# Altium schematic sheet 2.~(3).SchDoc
size 609 x 444 mm
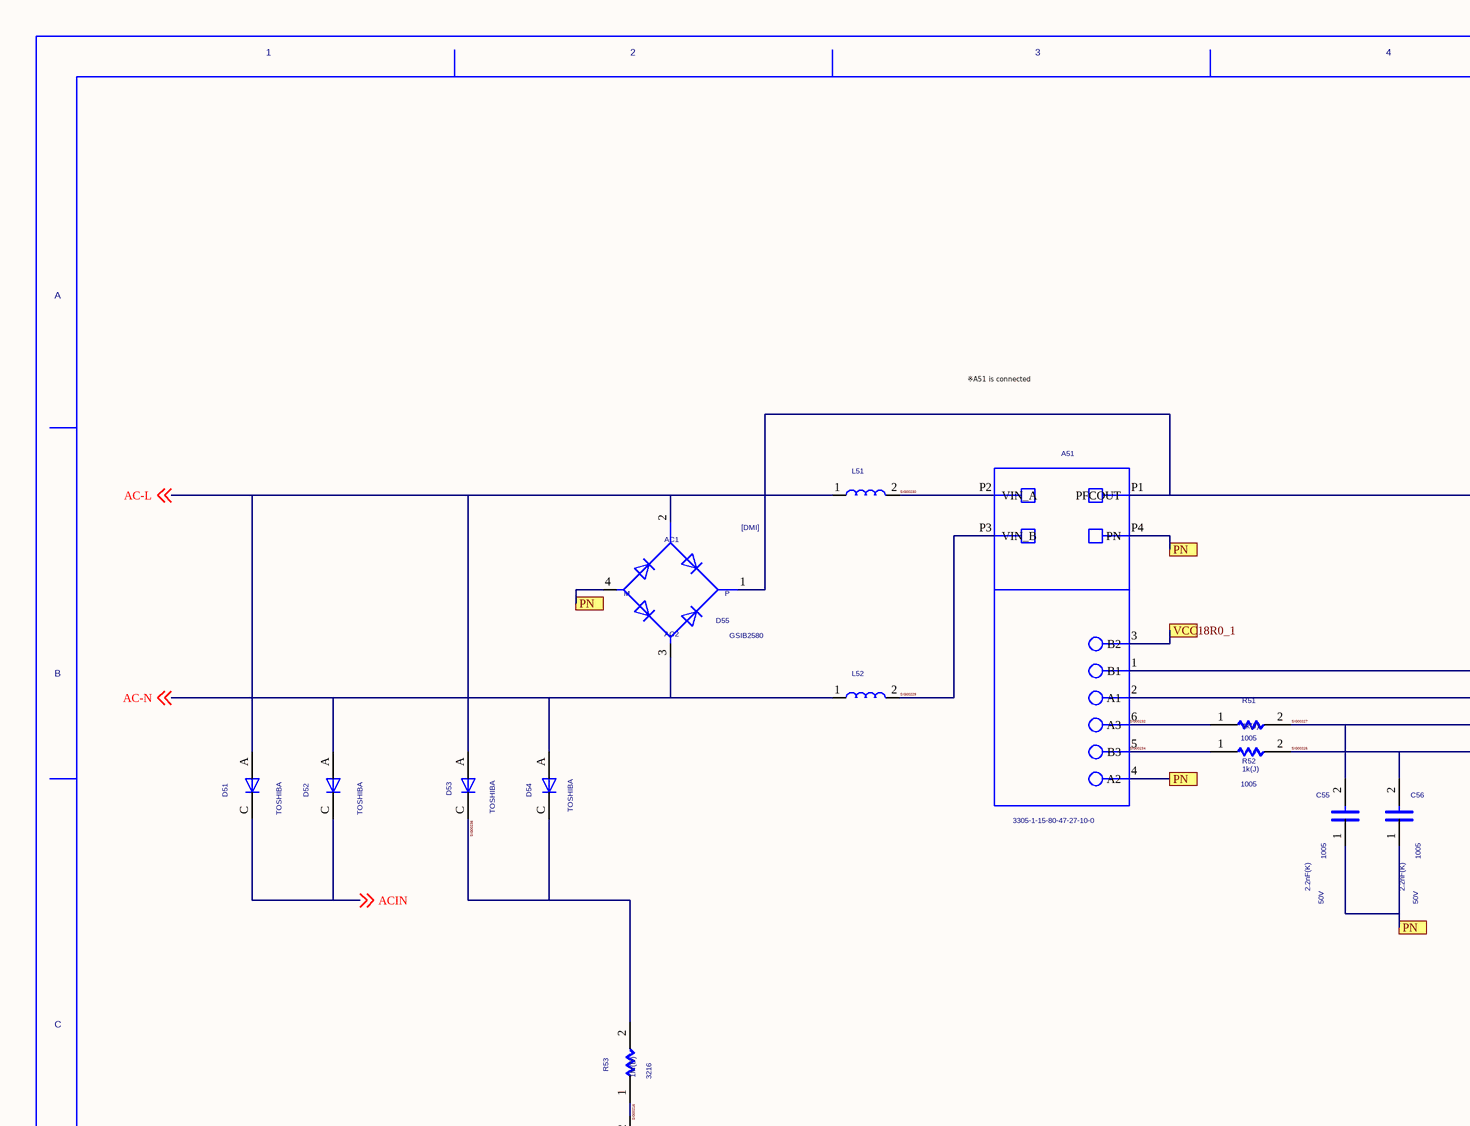
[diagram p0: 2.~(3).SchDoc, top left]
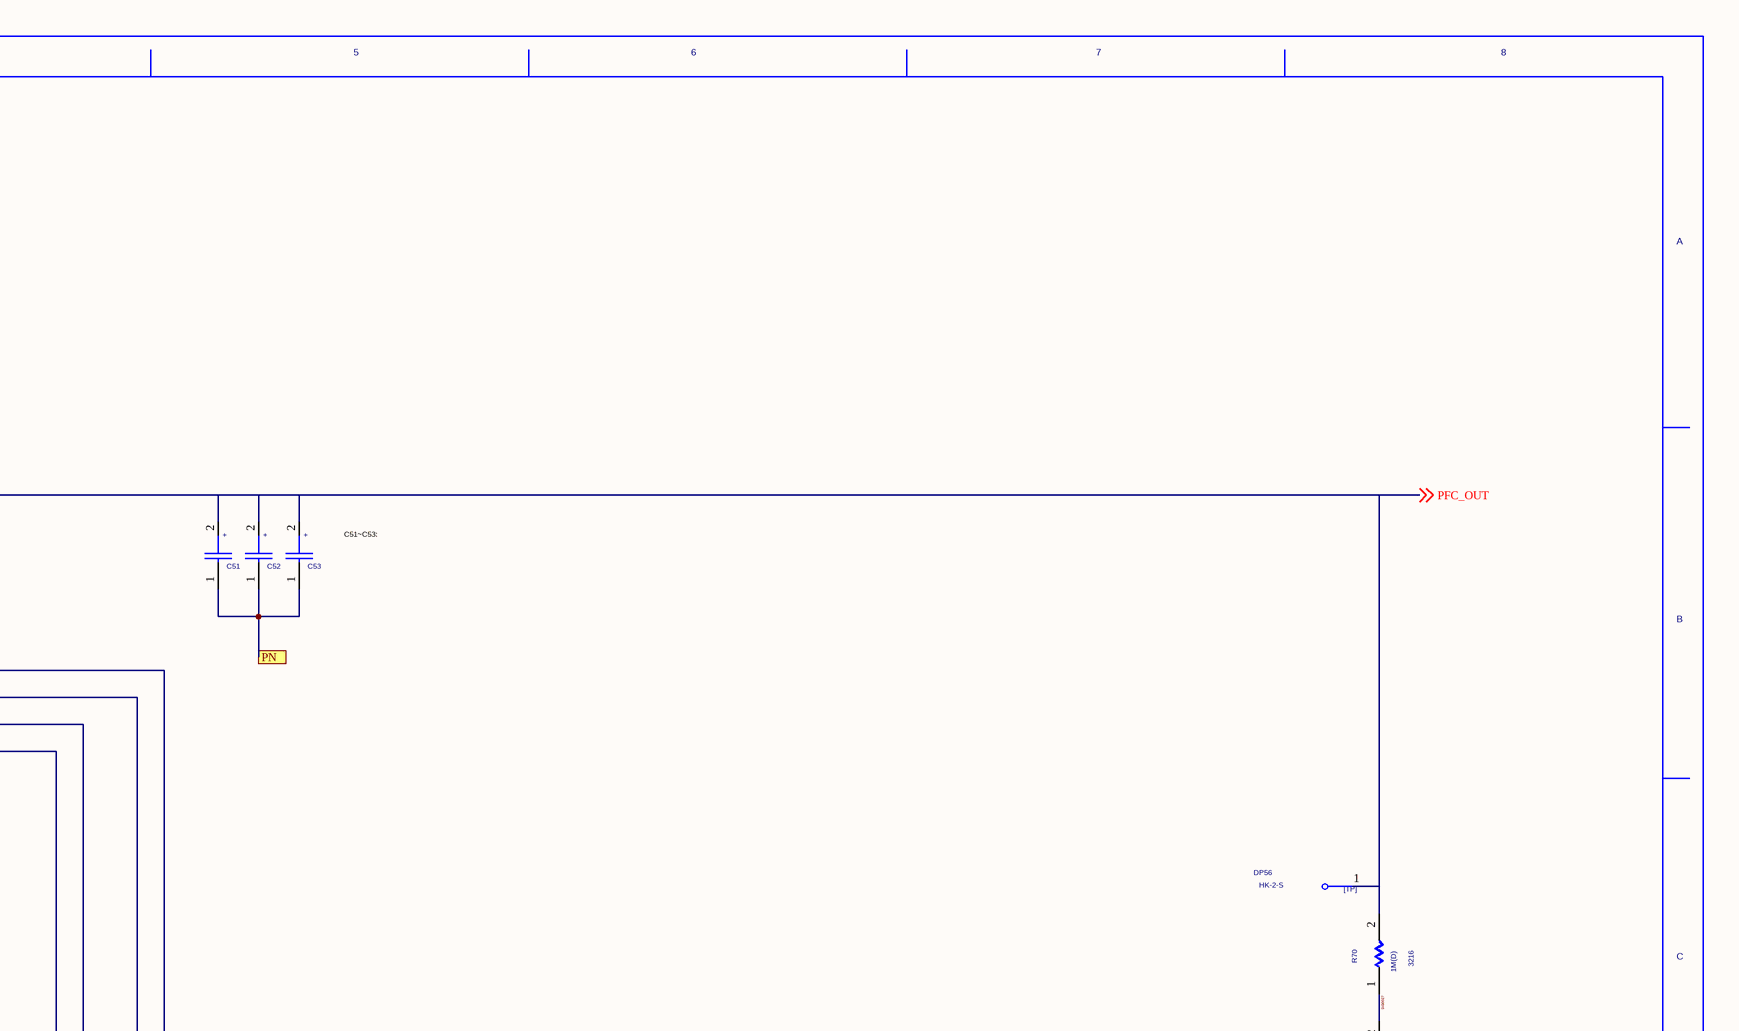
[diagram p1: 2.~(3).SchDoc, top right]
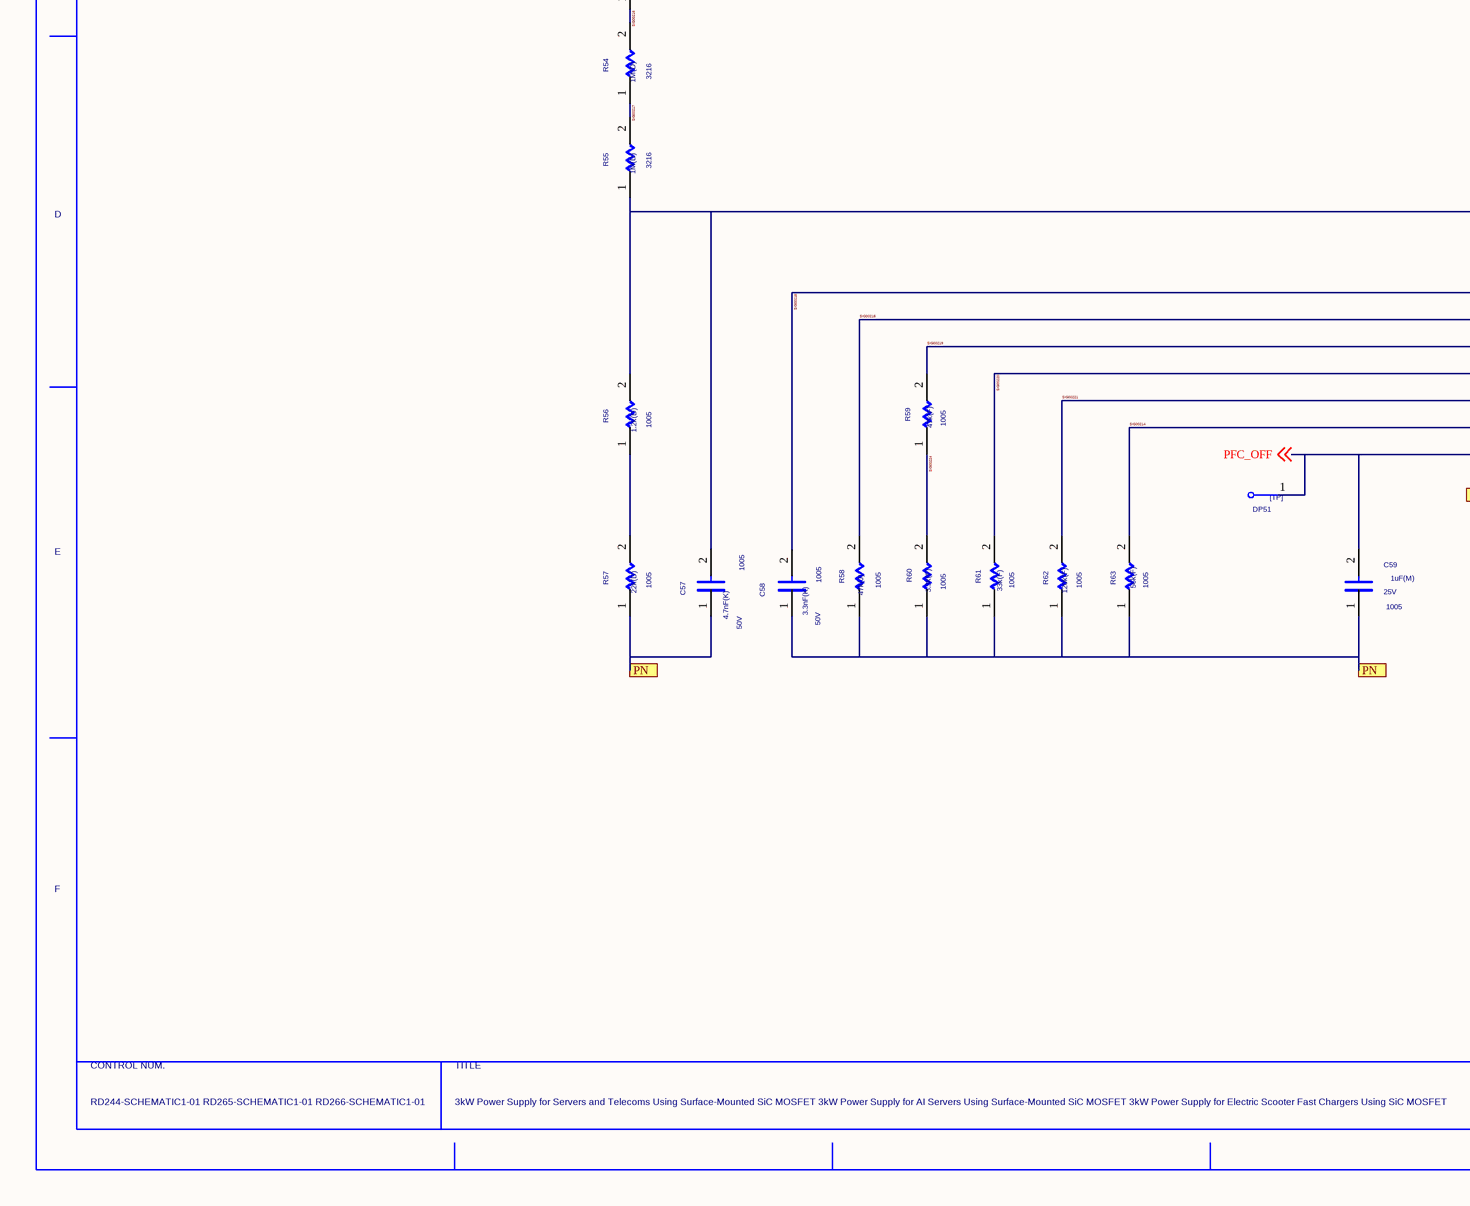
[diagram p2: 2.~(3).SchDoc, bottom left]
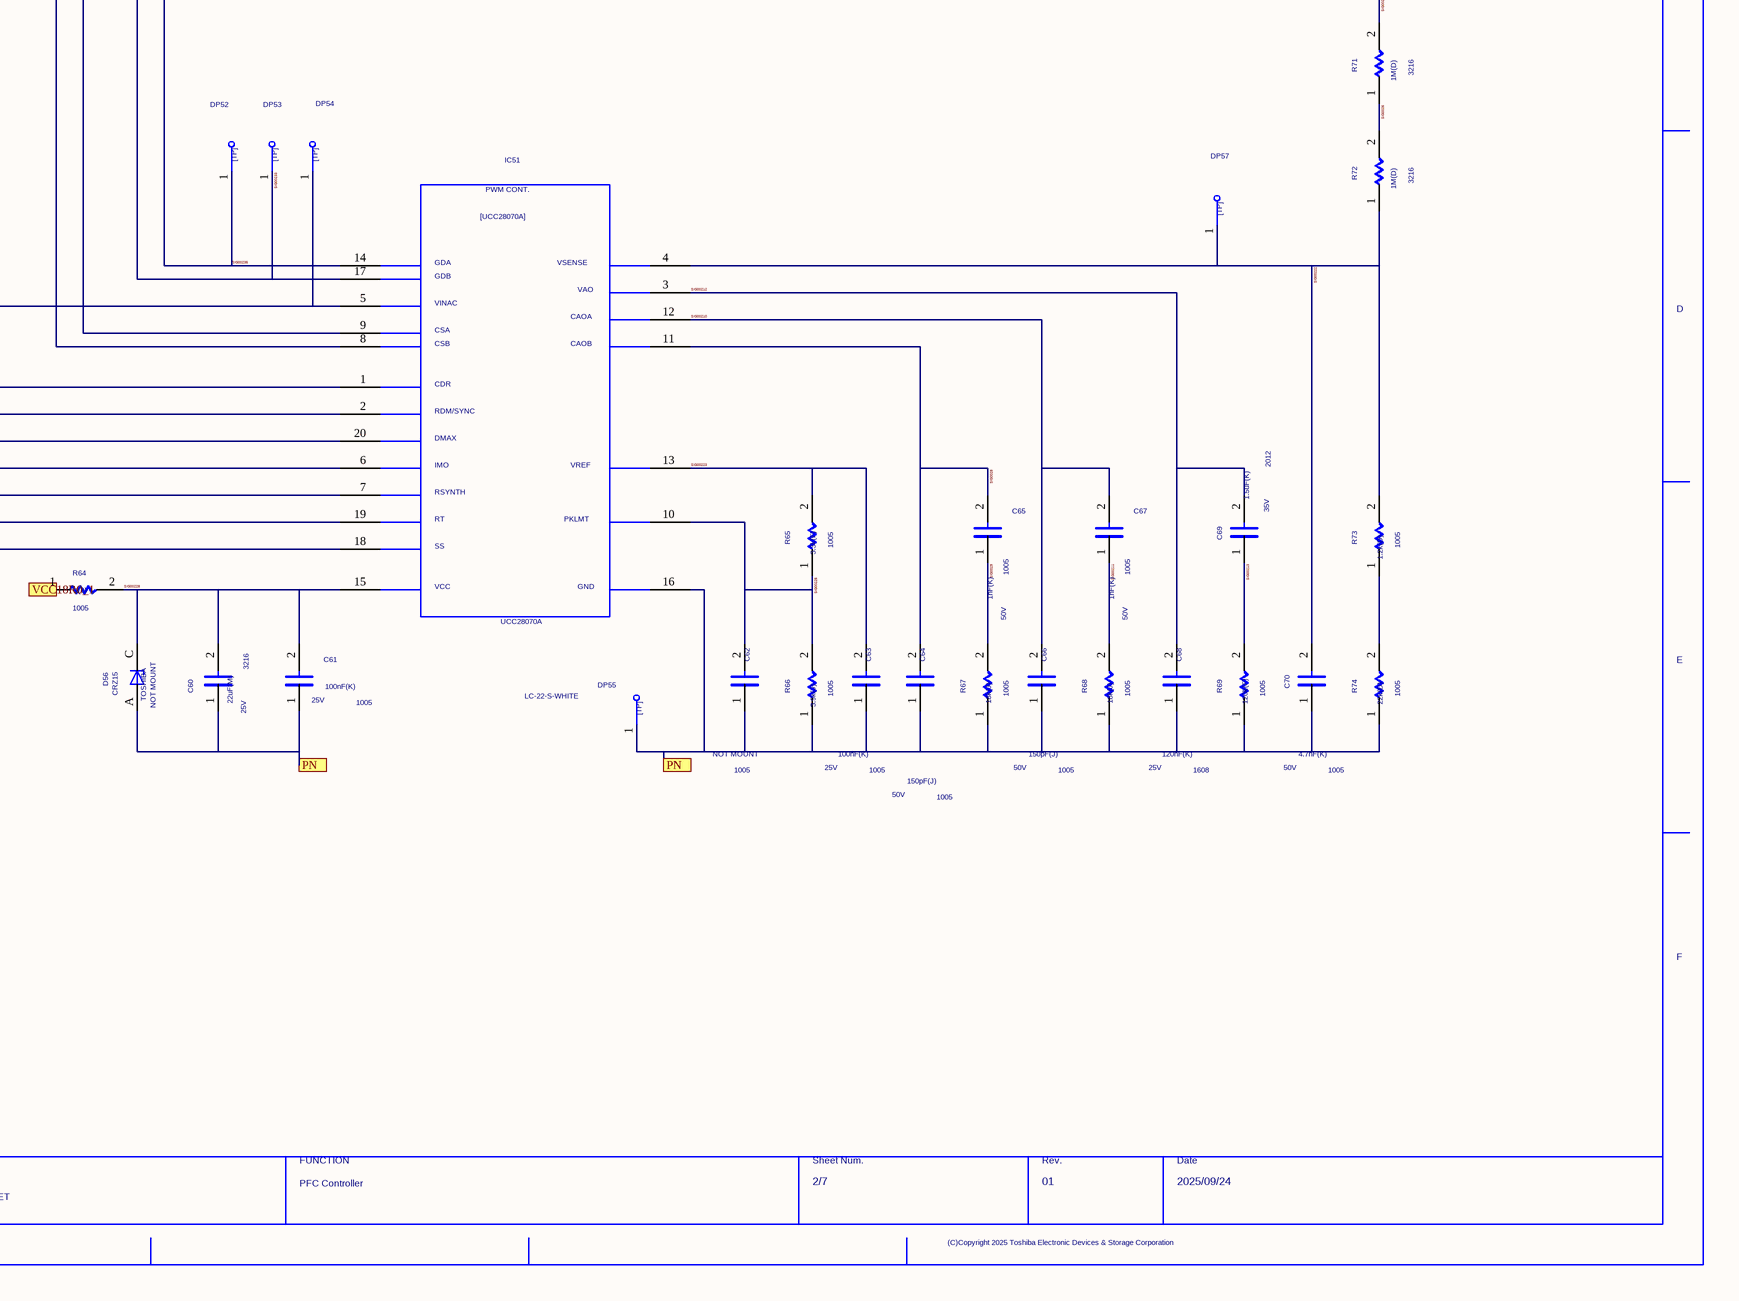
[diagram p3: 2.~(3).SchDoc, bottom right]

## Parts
A51  VAL3: 3305-1-15-80-47-27-10-0  (hidden comment: RD-244_PFC_UNIT1)
C51  EKHE421VSN102MA45Z  (value not drawn)
C52  EKHE421VSN102MA45Z  (value not drawn)
C53  EKHE421VSN102MA45Z  (value not drawn)
C55  VAL1: 2.2nF(K)  VAL2: 50V  SIZECODESMD: 1005  (hidden comment: C)
C56  VAL1: 2.2nF(K)  VAL2: 50V  SIZECODESMD: 1005  (hidden comment: C)
C57  VAL1: 4.7nF(K)  VAL2: 50V  SIZECODESMD: 1005  (hidden comment: C)
C58  VAL1: 3.3nF(K)  VAL2: 50V  SIZECODESMD: 1005  (hidden comment: C)
C59  VAL1: 1uF(M)  VAL2: 25V  SIZECODESMD: 1005  (hidden comment: C)
C60  VAL1: 22uF(M)  VAL2: 25V  SIZECODESMD: 3216  (hidden comment: C)
C61  VAL1: 100nF(K)  VAL2: 25V  SIZECODESMD: 1005  (hidden comment: C)
C62  NOTMOUNT: NOT MOUNT  SIZECODESMD: 1005  (hidden comment: C)
C63  VAL1: 100nF(K)  VAL2: 25V  SIZECODESMD: 1005  (hidden comment: C)
C64  VAL1: 150pF(J)  VAL2: 50V  SIZECODESMD: 1005  (hidden comment: C)
C65  VAL1: 1nF(K)  VAL2: 50V  SIZECODESMD: 1005  (hidden comment: C)
C66  VAL1: 150pF(J)  VAL2: 50V  SIZECODESMD: 1005  (hidden comment: C)
C67  VAL1: 1nF(K)  VAL2: 50V  SIZECODESMD: 1005  (hidden comment: C)
C68  VAL1: 120nF(K)  VAL2: 25V  SIZECODESMD: 1608  (hidden comment: C)
C69  VAL1: 1.5uF(K)  VAL2: 35V  SIZECODESMD: 2012  (hidden comment: GRM21BC71E106KE01)
C70  VAL1: 4.7nF(K)  VAL2: 50V  SIZECODESMD: 1005  (hidden comment: C)
D51  USERCOMPTEXT3: TOSHIBA  (hidden comment: CRG04A)
D52  USERCOMPTEXT3: TOSHIBA  (hidden comment: CRG04A)
D53  USERCOMPTEXT3: TOSHIBA  (hidden comment: CRG04A)
D54  USERCOMPTEXT3: TOSHIBA  (hidden comment: CRG04A)
D55  VAL3: GSIB2580  (hidden comment: DMI)
D56  NOTMOUNT: NOT MOUNT  USERCOMPTEXT3: TOSHIBA  VAL3: CRZ15  (hidden comment: ZD)
DP51  TP  (value not drawn)
DP52  TP  (value not drawn)
DP53  TP  (value not drawn)
DP54  TP  (value not drawn)
DP55  VAL3: LC-22-S-WHITE  (hidden comment: TP)
DP56  VAL3: HK-2-S  (hidden comment: TP)
DP57  TP  (value not drawn)
IC51  VAL3: UCC28070A  (hidden comment: L28070)
L51  TAM-30A131  (value not drawn)
L52  TAM-30A131  (value not drawn)
R51  VAL1: 1k(J)  SIZECODESMD: 1005  (hidden comment: R)
R52  VAL1: 1k(J)  SIZECODESMD: 1005  (hidden comment: R)
R53  VAL1: 1M(D)  SIZECODESMD: 3216  (hidden comment: R)
R54  VAL1: 1M(D)  SIZECODESMD: 3216  (hidden comment: R)
R55  VAL1: 1M(D)  SIZECODESMD: 3216  (hidden comment: R)
R56  VAL1: 1.2k(D)  SIZECODESMD: 1005  (hidden comment: R)
R57  VAL1: 22k(D)  SIZECODESMD: 1005  (hidden comment: R)
R58  VAL1: 47k(J)  SIZECODESMD: 1005  (hidden comment: R)
R59  VAL1: 47k(F)  SIZECODESMD: 1005  (hidden comment: R)
R60  VAL1: 3.3k(F)  SIZECODESMD: 1005  (hidden comment: R)
R61  VAL1: 33k(F)  SIZECODESMD: 1005  (hidden comment: R)
R62  VAL1: 120k(F)  SIZECODESMD: 1005  (hidden comment: R)
R63  VAL1: 56k(F)  SIZECODESMD: 1005  (hidden comment: R)
R64  VAL1: 1(J)  SIZECODESMD: 1005  (hidden comment: R)
R65  VAL1: 3.3k(F)  SIZECODESMD: 1005  (hidden comment: R)
R66  VAL1: 3.9k(J)  SIZECODESMD: 1005  (hidden comment: R)
R67  VAL1: 18k(J)  SIZECODESMD: 1005  (hidden comment: R)
R68  VAL1: 18k(J)  SIZECODESMD: 1005  (hidden comment: R)
R69  VAL1: 120k(F)  SIZECODESMD: 1005  (hidden comment: R)
R70  VAL1: 1M(D)  SIZECODESMD: 3216  (hidden comment: R)
R71  VAL1: 1M(D)  SIZECODESMD: 3216  (hidden comment: R)
R72  VAL1: 1M(D)  SIZECODESMD: 3216  (hidden comment: R)
R73  VAL1: 1.2k(D)  SIZECODESMD: 1005  (hidden comment: R)
R74  VAL1: 22k(D)  SIZECODESMD: 1005  (hidden comment: R)
U?  DATE: 2025/09/24  DRAWINGNUMBER: RD244-SCHEMATIC1-01 / RD265-SCHEMATIC1-01 / RD266-SCHEMATIC1-01  TITLE: 3kW Power Supply for Servers and Telecoms Using Surface-Mounted SiC MOSFET / 3kW Power Supply for AI Servers Using Surface-Mounted SiC MOSFET / 3kW Power Supply for Electric Scooter Fast Chargers Using SiC MOSFET  FUNCTION: PFC Controller  SHEETNUMBER: 2/7  REVISION: 01  (hidden comment: WAKU_DEF_A3_1)

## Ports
PN, VCC18R0_1

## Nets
$BN000001: R73.1 R74.2
$BN000002: R56.1 R57.2
AC-L: D51.A D53.A D55.2 L51.1 ; off-sheet AC-L
AC-N: D52.A D54.A D55.3 L52.1 ; off-sheet AC-N
ACIN: D51.C D52.C ; off-sheet ACIN
PFC_OFF: C59.2 DP51.1 IC51.18 ; off-sheet PFC_OFF
PFC_OUT: A51.P1(PFCOUT) C51.2 C52.2 C53.2 D55.1 DP56.1 R70.2 ; off-sheet PFC_OUT
PN: A51.4(A2) A51.P4(PN) C51.1 C52.1 C53.1 C55.1 C56.1 C57.1 C58.1 C59.1 C60.1 C61.1 C62.1 C63.1 C64.1 C66.1 C68.1 C70.1 D55.4 D56.A DP55.1 IC51.16 R57.1 R58.1 R60.1 R61.1 R62.1 R63.1 R66.1 R67.1 R68.1 R69.1 R74.1 ; port PN
SIG0026: R71.1 R72.2
SIG0027: R70.1 R71.2
SIG0028: C64.2 C65.2 IC51.11
SIG0029: C65.1 R67.2
SIG62: C57.2 DP54.1 IC51.5 R55.1 R56.2
SIG00210: C66.2 C67.2 IC51.12
SIG00211: C67.1 R68.2
SIG00212: C68.2 C69.2 IC51.3
SIG00213: C69.1 R69.2
SIG00214: IC51.19 R63.2
SIG00215: IC51.2 R58.2
SIG00216: R53.1 R54.2
SIG00217: R54.1 R55.2
SIG00218: C58.2 IC51.1
SIG00219: IC51.20 R59.2
SIG00220: IC51.6 R61.2
SIG00221: IC51.7 R62.2
SIG00222: C70.2 DP57.1 IC51.4 R72.1 R73.2
SIG00223: C63.2 IC51.13 R65.2
SIG00224: R59.1 R60.2
SIG00225: C62.2 IC51.10 R65.1 R66.2
SIG00226: C56.2 IC51.8 R52.2
SIG00227: C55.2 IC51.9 R51.2
SIG00228: C60.2 C61.2 D56.C IC51.15 R64.2
SIG00229: A51.P3(VIN_B) L52.2
SIG00230: A51.P2(VIN_A) L51.2
SIG00232: A51.6(A3) R51.1
SIG00233: A51.2(A1) DP53.1 IC51.17
SIG00234: A51.5(B3) R52.1
SIG00235: A51.1(B1) DP52.1 IC51.14
SIG00236: D53.C D54.C R53.2
VCC18R0_1: A51.3(B2) R64.1 ; port VCC18R0_1

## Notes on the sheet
- ※A51 is connected
  to CN601 and CN602 of RD244-SCHEMATICS2
- (near C53) C51~C53:

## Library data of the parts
A51 = RD-244_PFC_UNIT1: TIME: 11:34:46; UPDATEUSER: t5459927; UPDATETIME: 16:41:12; SAVECOUNT: 29; SAVEAREA0: -20981,-344,43891,33349; OriginalSymbolOrigin: (0,63500)
C51-C53 = EKHE421VSN102MA45Z: SQ_PART_MODEL: CON_390U; SAVEAREA0: -1450,-153,20294,13055; SAVECOUNT: 53; TIME: 15:02:55; UPDATEUSER: t4887876; UPDATETIME: 08:41:08; VAL1: 420V; VAL2: 1010uF(M); OriginalSymbolOrigin: (2540,10160); MAXGCOUNT: 1; SIZECODESMD: DIP; ADSCNVFLAG: ON
C55 C57-C59 C63-C67 C70 = C_Dup2: OriginalSymbolOrigin: (2540,7620); COMP: PRT_52; MAXGCOUNT: 1; SAVECOUNT: 0
C56 = C_Dup2: OriginalSymbolOrigin: (2540,7620); COMP: PRT_52; OLDCOMPONENTID: 99; MAXGCOUNT: 1; SAVECOUNT: 0
C60 = C_Dup1: OriginalSymbolOrigin: (2540,7620); COMP: PRT_46; SAVECOUNT: 0
C61 = C_Dup2: SQ_PART_MODEL: CON_100N; OriginalSymbolOrigin: (2540,7620); COMP: PRT_52; MAXGCOUNT: 1; ADSCNVFLAG: ON; ADSCOMPONENTNAME: C_1005; SAVECOUNT: 0
C62 = C_Dup2: VAL1: 100nF(K); VAL2: 25V; OriginalSymbolOrigin: (2540,7620); COMP: PRT_52; MAXGCOUNT: 1; SAVECOUNT: 0
C68 = C_Dup2: OriginalSymbolOrigin: (2540,7620); COMP: PRT_48; MAXGCOUNT: 1; SAVECOUNT: 0
C69 = GRM21BC71E106KE01: TIME: 10:25:11; UPDATEUSER: t4887876; UPDATETIME: 16:23:00; SAVECOUNT: 11; MAKER: Murata; OriginalSymbolOrigin: (2540,7620); CHIPSIZE: 1005; MAXGCOUNT: 1
D51-D54 = CRG04A: SAVEAREA0: -4630,-153,17114,13055; TIME: 14:49:55; UPDATEUSER: t6860224; UPDATETIME: 10:39:47; SAVECOUNT: 14; MAXV: 600V; MAXI: 1A; OriginalSymbolOrigin: (5080,5080); USERCOMPTEXT2: 600V,1A; MAXGCOUNT: 1
D55 = DMI: SAVECOUNT: 7; SAVEAREA0: -7762,-358,32649,26224; TIME: 10:09:47; UPDATEUSER: fukuda-y; UPDATETIME: 17:30:39; OriginalSymbolOrigin: (0,25400); COMP: PRT_53; MAXGCOUNT: 1
D56 = ZD: SAVEAREA0: -4630,-153,17114,13055; TIME: 14:49:55; UPDATEUSER: fukuda-y; UPDATETIME: 08:18:42; SAVECOUNT: 6; OriginalSymbolOrigin: (5080,5080); COMP: PRT_6; MAXGCOUNT: 1
DP51-DP54 DP57 = TP: TIME: 16:12:21; UPDATEUSER: fukuda-y; UPDATETIME: 16:18:11; SAVECOUNT: 2; SAVEAREA0: -242,-92,12810,7836; OriginalSymbolOrigin: (0,7620); USERCOMPTEXT1: Φ1.5mm; COMP: DTP815
DP55 = TP: TIME: 16:12:21; UPDATEUSER: fukuda-y; UPDATETIME: 16:18:11; SAVECOUNT: 2; SAVEAREA0: -242,-92,12810,7836; OriginalSymbolOrigin: (0,7620); COMP: PRT_49
DP56 = TP: TIME: 16:12:21; UPDATEUSER: fukuda-y; UPDATETIME: 16:18:11; SAVECOUNT: 2; SAVEAREA0: -242,-92,12810,7836; OriginalSymbolOrigin: (0,7620); COMP: PRT_44
IC51 = L28070: SAVEAREA0: -12344,-1037,78634,87348; SAVECOUNT: 29; TIME: 15:02:55; UPDATEUSER: cae; UPDATETIME: 14:36:12; OriginalSymbolOrigin: (7620,83820); COMP: PRT_59
L51 L52 = TAM-30A131: VAL1: 100uH min.; VAL2: 30A; TIME: 14:26:02; UPDATEUSER: t4887876; SAVECOUNT: 1; OriginalSymbolOrigin: (2540,5080)
R51 = R_Dup2: VAL2: 63mW; OriginalSymbolOrigin: (5080,5080); COMP: GDM010004481; CHIPSIZE: 1608; OLDCOMPONENTID: 100; MAXGCOUNT: 1; SAVECOUNT: 0
R52 R57 R58 R61 R63 R64 R67-R69 R74 = R_Dup2: VAL2: 63mW; OriginalSymbolOrigin: (5080,5080); COMP: GDM010004481; CHIPSIZE: 1608; MAXGCOUNT: 1; SAVECOUNT: 0
R53-R55 R70-R72 = R_Dup2: VAL2: 250mW; OriginalSymbolOrigin: (5080,5080); COMP: PRT_5; CHIPSIZE: 1608; MAXGCOUNT: 1; SAVECOUNT: 0
R56 R59 R60 R62 R65 R66 R73 = R_Dup2: VAL2: 63mW; OriginalSymbolOrigin: (5080,5080); MAXGCOUNT: 1; COMP: GDM010004481; CHIPSIZE: 1608; SAVECOUNT: 0
U? = WAKU_DEF_A3_1: PLOTTIME: HH:MM; SAVEAREA0: 96913,-567914,509243,-368858; TIME: 14:20:16; UPDATEUSER: t5459927; UPDATETIME: 13:12:48; SAVECOUNT: 3; ZONEOFFSETX: 36; ZONEOFFSETY: -24; OriginalSymbolOrigin: (12700,-12700); SHTSAVECOUNT: 140; PAGENUMBER: 2; DESIGNED: TOSHIBA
